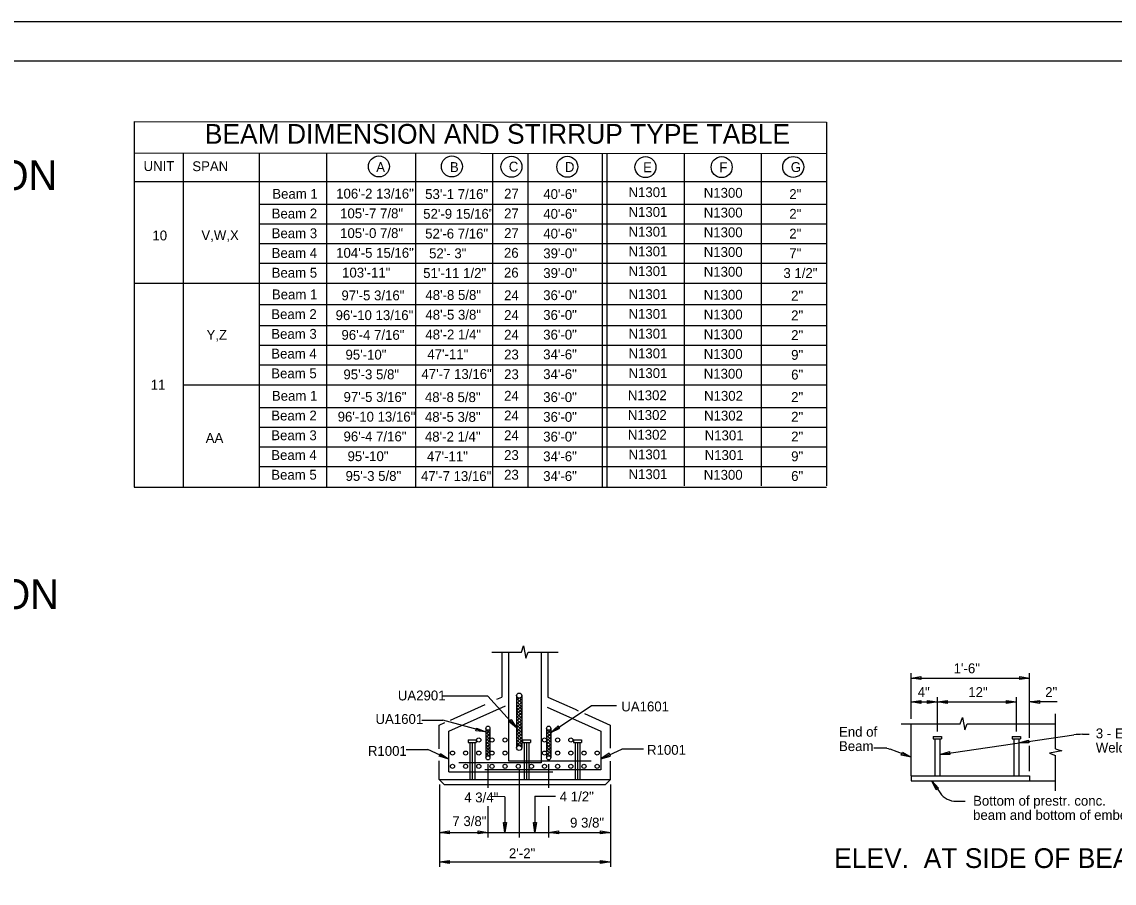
# Model space of a CAD drawing. Extents: x -50.5 to -14.4, y 42.4 to 64.4.
# Drawn here: x -37.02 to -23.18, y 53.54 to 64.45 of the extents above; entities that cross this region are included whole.
import ezdxf

# ---------------------------------------------------------------- set-up
doc = ezdxf.new("R2010")
doc.units = 0
for name, color, linetype in [('BR_AUTO DIMENSION', 7, 'Continuous'), ('BR_BORDER LINES', 7, 'Continuous'), ('BR_CENTER LINES', 7, 'Continuous'), ('BR_PRESTRESSED BEAM', 7, 'Continuous'), ('BR_REBAR', 7, 'Continuous'), ('BR_STRUCTURAL STEEL', 7, 'Continuous'), ('BR_TABLE LINES', 7, 'Continuous'), ('BR_TEXT', 7, 'Continuous'), ('Level 31', 7, 'Continuous')]:
    doc.layers.add(name, color=color, linetype=linetype)

msp = doc.modelspace()

# ---------------------------------------------------------------- linework, layer by layer
at = {"layer": 'BR_AUTO DIMENSION'}
for p, q in [((-31.065, 56.469), (-30.69, 56.469)), ((-30.603, 56.469), (-30.223, 56.469)), ((-25.754, 55.623), (-25.754, 56.2)), ((-24.254, 55.384), (-24.254, 56.2)), ((-25.754, 56.138), (-24.254, 56.138)), ((-31.115, 55.908), (-31.686, 55.908)), ((-31.115, 55.908), (-30.75, 55.509)), ((-25.754, 55.623), (-25.754, 55.899)), ((-25.421, 55.461), (-25.421, 55.899)), ((-24.421, 55.461), (-24.421, 55.899)), ((-30.318, 55.451), (-29.807, 55.789)), ((-29.486, 55.788), (-29.807, 55.789)), ((-25.754, 55.836), (-25.421, 55.836)), ((-25.421, 55.836), (-24.421, 55.836)), ((-23.904, 55.836), (-24.254, 55.836)), ((-23.924, 55.245), (-23.924, 55.686)), ((-31.95, 55.606), (-31.686, 55.607)), ((-31.139, 55.46), (-31.686, 55.607)), ((-25.879, 55.561), (-25.131, 55.561)), ((-25.044, 55.561), (-23.924, 55.561)), ((-25.39, 55.172), (-23.692, 55.42)), ((-23.584, 55.427), (-23.5, 55.427)), ((-32.147, 55.233), (-31.873, 55.233)), ((-31.608, 55.113), (-31.873, 55.233)), ((-29.682, 55.117), (-29.417, 55.237)), ((-29.143, 55.237), (-29.417, 55.237)), ((-26.061, 55.252), (-26.228, 55.252)), ((-25.754, 55.138), (-26.018, 55.237)), ((-24.254, 54.961), (-24.254, 55.281)), ((-23.924, 54.711), (-23.924, 55.158)), ((-31.113, 55.047), (-31.113, 54.751)), ((-30.717, 54.982), (-30.717, 54.122)), ((-30.344, 55.047), (-30.344, 54.751)), ((-31.728, 54.793), (-31.728, 53.748)), ((-29.561, 54.793), (-29.561, 54.286)), ((-25.493, 54.836), (-25.387, 54.686)), ((-30.517, 54.644), (-30.258, 54.645)), ((-30.517, 54.644), (-30.517, 54.184)), ((-31.113, 54.519), (-31.113, 54.122)), ((-30.898, 54.637), (-31.079, 54.638)), ((-30.898, 54.637), (-30.898, 54.184)), ((-30.344, 54.519), (-30.344, 54.122)), ((-25.182, 54.579), (-25.071, 54.579)), ((-29.561, 54.445), (-29.561, 54.122)), ((-31.728, 54.184), (-31.009, 54.184)), ((-31.009, 54.184), (-30.342, 54.184)), ((-30.342, 54.184), (-29.561, 54.184)), ((-29.561, 54.122), (-29.561, 53.748)), ((-31.728, 53.811), (-29.561, 53.811))]:
    msp.add_line(p, q, dxfattribs=at)
for points in [[(-30.69, 56.469), (-30.661, 56.547), (-30.632, 56.392), (-30.603, 56.469)], [(-25.131, 55.561), (-25.102, 55.638), (-25.073, 55.484), (-25.044, 55.561)], [(-23.924, 55.245), (-23.847, 55.216), (-24.001, 55.187), (-23.924, 55.158)]]:
    msp.add_lwpolyline(points, dxfattribs=at)
for points in [[(-25.629, 56.119), (-25.754, 56.138), (-25.629, 56.157)], [(-24.379, 56.157), (-24.254, 56.138), (-24.379, 56.119)], [(-25.629, 55.817), (-25.754, 55.836), (-25.629, 55.855)], [(-25.546, 55.855), (-25.421, 55.836), (-25.546, 55.817)], [(-25.296, 55.817), (-25.421, 55.836), (-25.296, 55.855)], [(-24.546, 55.855), (-24.421, 55.836), (-24.546, 55.817)], [(-24.129, 55.817), (-24.254, 55.836), (-24.129, 55.855)], [(-30.82, 55.614), (-30.75, 55.509), (-30.848, 55.588)], [(-31.257, 55.506), (-31.139, 55.46), (-31.265, 55.469)], [(-30.224, 55.535), (-30.318, 55.451), (-30.204, 55.504)], [(-24.263, 55.317), (-24.39, 55.318), (-24.269, 55.354)], [(-25.865, 55.199), (-25.754, 55.138), (-25.878, 55.164)], [(-25.263, 55.171), (-25.39, 55.172), (-25.269, 55.208)], [(-31.714, 55.182), (-31.608, 55.113), (-31.73, 55.148)], [(-29.576, 55.186), (-29.682, 55.117), (-29.56, 55.152)], [(-25.436, 54.723), (-25.493, 54.836), (-25.406, 54.745)], [(-30.88, 54.309), (-30.898, 54.184), (-30.917, 54.309)], [(-30.499, 54.309), (-30.517, 54.184), (-30.536, 54.309)], [(-31.603, 54.165), (-31.728, 54.184), (-31.603, 54.203)], [(-31.238, 54.203), (-31.113, 54.184), (-31.238, 54.165)], [(-30.219, 54.165), (-30.344, 54.184), (-30.219, 54.203)], [(-29.686, 54.203), (-29.561, 54.184), (-29.686, 54.165)], [(-31.603, 53.792), (-31.728, 53.811), (-31.603, 53.83)], [(-29.686, 53.83), (-29.561, 53.811), (-29.686, 53.792)]]:
    msp.add_lwpolyline(points, close=True, dxfattribs=at)
for centre in [(-32.494, 62.617), (-31.57, 62.617), (-30.815, 62.613), (-30.108, 62.613), (-29.118, 62.609), (-28.153, 62.609), (-27.247, 62.611)]:
    msp.add_circle(centre, 0.133, dxfattribs=at)
for centre, radius, start, end in [((-23.584, 54.677), 0.75, 90, 98.305), ((-26.106, 55.002), 0.25, 69.5828, 90), ((-25.182, 54.829), 0.25, 215.0738, 270)]:
    msp.add_arc(centre, radius, start, end, dxfattribs=at)
at = {"layer": 'BR_BORDER LINES'}
for p, q in [((-15.019, 63.949), (-48.685, 63.949)), ((-35.595, 63.186), (-35.595, 58.558)), ((-35.594, 63.186), (-26.824, 63.179)), ((-26.824, 63.18), (-26.824, 58.572)), ((-35.595, 62.788), (-26.824, 62.78)), ((-29.665, 62.783), (-29.665, 58.558)), ((-29.606, 62.783), (-29.606, 58.558)), ((-35.595, 58.558), (-26.824, 58.558))]:
    msp.add_line(p, q, dxfattribs=at)
at = {"layer": 'BR_CENTER LINES'}
for p, q in [((-31.312, 55.324), (-31.312, 54.855)), ((-30.625, 55.324), (-30.625, 54.855)), ((-29.979, 55.324), (-29.979, 54.855))]:
    msp.add_line(p, q, dxfattribs=at)
at = {"layer": 'BR_PRESTRESSED BEAM'}
for p, q in [((-30.938, 56.469), (-30.938, 55.899)), ((-30.354, 56.469), (-30.354, 55.899)), ((-31.002, 55.87), (-30.938, 55.898)), ((-30.354, 55.898), (-30.01, 55.744)), ((-31.586, 55.607), (-31.146, 55.805)), ((-30.01, 55.744), (-29.971, 55.726)), ((-29.891, 55.69), (-29.563, 55.543)), ((-31.729, 55.543), (-31.657, 55.575)), ((-31.729, 55.242), (-31.729, 55.543)), ((-29.563, 55.543), (-29.563, 55.252)), ((-25.754, 54.899), (-25.754, 55.561)), ((-31.729, 54.855), (-31.729, 55.09)), ((-29.563, 55.085), (-29.563, 54.855)), ((-31.729, 54.855), (-29.563, 54.855)), ((-24.254, 54.836), (-23.924, 54.836))]:
    msp.add_line(p, q, dxfattribs=at)
at = {"layer": 'BR_REBAR'}
for p, q in [((-30.854, 56.469), (-30.854, 55.091)), ((-30.438, 56.469), (-30.438, 55.066)), ((-30.75, 55.917), (-30.75, 55.254)), ((-30.75, 55.901), (-30.747, 55.904)), ((-30.75, 55.885), (-30.685, 55.82)), ((-30.707, 55.886), (-30.685, 55.864)), ((-30.685, 55.917), (-30.685, 55.254)), ((-31.608, 55.466), (-30.889, 55.789)), ((-30.75, 55.857), (-30.722, 55.885)), ((-30.75, 55.813), (-30.685, 55.878)), ((-30.75, 55.841), (-30.685, 55.776)), ((-30.75, 55.768), (-30.685, 55.833)), ((-30.75, 55.804), (-30.685, 55.739)), ((-30.75, 55.724), (-30.685, 55.789)), ((-30.75, 55.768), (-30.685, 55.702)), ((-30.362, 55.771), (-29.682, 55.465)), ((-30.75, 55.68), (-30.685, 55.745)), ((-30.75, 55.731), (-30.685, 55.666)), ((-30.75, 55.636), (-30.685, 55.701)), ((-30.75, 55.694), (-30.685, 55.629)), ((-30.75, 55.592), (-30.685, 55.657)), ((-30.75, 55.657), (-30.685, 55.592)), ((-30.75, 55.62), (-30.685, 55.555)), ((-30.75, 55.547), (-30.685, 55.612)), ((-31.139, 55.504), (-31.139, 55.129)), ((-31.139, 55.488), (-31.087, 55.436)), ((-31.139, 55.473), (-31.129, 55.483)), ((-31.139, 55.429), (-31.087, 55.481)), ((-31.097, 55.483), (-31.087, 55.473)), ((-31.087, 55.504), (-31.087, 55.129)), ((-30.75, 55.583), (-30.685, 55.518)), ((-30.75, 55.503), (-30.685, 55.568)), ((-30.75, 55.547), (-30.685, 55.482)), ((-30.75, 55.459), (-30.685, 55.524)), ((-30.75, 55.51), (-30.685, 55.445)), ((-30.75, 55.415), (-30.685, 55.48)), ((-30.75, 55.473), (-30.685, 55.408)), ((-30.37, 55.504), (-30.37, 55.129)), ((-30.37, 55.488), (-30.318, 55.436)), ((-30.37, 55.473), (-30.36, 55.483)), ((-30.37, 55.429), (-30.318, 55.481)), ((-30.329, 55.483), (-30.318, 55.473)), ((-30.318, 55.504), (-30.318, 55.129)), ((-31.608, 54.952), (-31.608, 55.466)), ((-31.139, 55.452), (-31.087, 55.4)), ((-31.139, 55.384), (-31.087, 55.436)), ((-31.139, 55.415), (-31.087, 55.363)), ((-31.139, 55.34), (-31.087, 55.392)), ((-31.139, 55.378), (-31.087, 55.326)), ((-31.139, 55.296), (-31.087, 55.348)), ((-31.139, 55.341), (-31.087, 55.289)), ((-30.75, 55.371), (-30.685, 55.436)), ((-30.75, 55.436), (-30.685, 55.371)), ((-30.75, 55.399), (-30.685, 55.334)), ((-30.75, 55.326), (-30.685, 55.392)), ((-30.75, 55.362), (-30.685, 55.297)), ((-30.75, 55.282), (-30.685, 55.347)), ((-30.37, 55.452), (-30.318, 55.4)), ((-30.37, 55.384), (-30.318, 55.436)), ((-30.37, 55.415), (-30.318, 55.363)), ((-30.37, 55.34), (-30.318, 55.392)), ((-30.37, 55.378), (-30.318, 55.326)), ((-30.37, 55.296), (-30.318, 55.348)), ((-30.37, 55.341), (-30.318, 55.289)), ((-29.682, 55.465), (-29.682, 54.975)), ((-31.139, 55.252), (-31.087, 55.304)), ((-31.139, 55.304), (-31.087, 55.252)), ((-31.139, 55.267), (-31.087, 55.215)), ((-31.139, 55.208), (-31.087, 55.26)), ((-31.139, 55.231), (-31.087, 55.179)), ((-31.139, 55.163), (-31.087, 55.216)), ((-31.139, 55.194), (-31.087, 55.142)), ((-30.75, 55.326), (-30.691, 55.267)), ((-30.75, 55.289), (-30.735, 55.274)), ((-30.709, 55.279), (-30.685, 55.303)), ((-30.37, 55.252), (-30.318, 55.304)), ((-30.37, 55.304), (-30.318, 55.252)), ((-30.37, 55.267), (-30.318, 55.215)), ((-30.37, 55.208), (-30.318, 55.26)), ((-30.37, 55.231), (-30.318, 55.179)), ((-30.37, 55.163), (-30.318, 55.216)), ((-30.37, 55.194), (-30.318, 55.142)), ((-30.438, 55.066), (-31.483, 55.066)), ((-31.139, 55.157), (-31.131, 55.148)), ((-31.105, 55.154), (-31.087, 55.171)), ((-30.854, 55.091), (-29.807, 55.091)), ((-30.37, 55.157), (-30.362, 55.148)), ((-30.336, 55.154), (-30.318, 55.171)), ((-31.608, 54.952), (-30.29, 54.952)), ((-29.682, 54.975), (-31.153, 54.975))]:
    msp.add_line(p, q, dxfattribs=at)
for centre, radius in [((-30.717, 55.917), 0.0326), ((-31.113, 55.504), 0.026), ((-30.344, 55.504), 0.026), ((-31.229, 55.355), 0.026), ((-31.062, 55.355), 0.026), ((-30.896, 55.355), 0.026), ((-30.397, 55.355), 0.026), ((-30.23, 55.355), 0.026), ((-30.063, 55.355), 0.026), ((-31.562, 55.189), 0.026), ((-31.396, 55.189), 0.026), ((-31.229, 55.189), 0.026), ((-31.062, 55.189), 0.026), ((-30.896, 55.189), 0.026), ((-30.717, 55.254), 0.0326), ((-30.397, 55.189), 0.026), ((-30.23, 55.189), 0.026), ((-30.063, 55.189), 0.026), ((-29.897, 55.189), 0.026), ((-29.73, 55.189), 0.026), ((-31.113, 55.129), 0.026), ((-30.344, 55.129), 0.026), ((-31.562, 55.022), 0.026), ((-31.396, 55.022), 0.026), ((-31.229, 55.022), 0.026), ((-31.062, 55.022), 0.026), ((-30.896, 55.022), 0.026), ((-30.729, 55.022), 0.026), ((-30.562, 55.022), 0.026), ((-30.397, 55.022), 0.026), ((-30.23, 55.022), 0.026), ((-30.063, 55.022), 0.026), ((-29.897, 55.022), 0.026), ((-29.73, 55.022), 0.026)]:
    msp.add_circle(centre, radius, dxfattribs=at)
at = {"layer": 'BR_STRUCTURAL STEEL'}
for p, q in [((-31.364, 55.355), (-31.364, 55.324)), ((-31.364, 55.355), (-31.26, 55.355)), ((-31.26, 55.355), (-31.26, 55.324)), ((-30.677, 55.355), (-30.573, 55.355)), ((-30.677, 55.355), (-30.677, 55.324)), ((-30.573, 55.355), (-30.573, 55.324)), ((-30.031, 55.355), (-29.927, 55.355)), ((-30.031, 55.355), (-30.031, 55.324)), ((-29.927, 55.355), (-29.927, 55.324)), ((-25.473, 55.399), (-25.369, 55.399)), ((-25.473, 55.399), (-25.473, 55.368)), ((-25.473, 55.368), (-25.369, 55.368)), ((-25.452, 55.368), (-25.452, 54.899)), ((-25.39, 55.368), (-25.39, 54.899)), ((-25.369, 55.399), (-25.369, 55.368)), ((-24.473, 55.399), (-24.369, 55.399)), ((-24.473, 55.399), (-24.473, 55.368)), ((-24.473, 55.368), (-24.369, 55.368)), ((-24.452, 55.368), (-24.452, 54.899)), ((-24.452, 55.368), (-24.452, 54.899)), ((-24.39, 55.368), (-24.39, 54.899)), ((-24.369, 55.399), (-24.369, 55.368)), ((-31.364, 55.324), (-31.26, 55.324)), ((-31.343, 55.324), (-31.343, 54.855)), ((-31.281, 55.324), (-31.281, 54.855)), ((-30.677, 55.324), (-30.573, 55.324)), ((-30.656, 55.324), (-30.656, 54.855)), ((-30.593, 55.324), (-30.593, 54.855)), ((-30.031, 55.324), (-29.927, 55.324)), ((-30.01, 55.324), (-30.01, 54.855)), ((-29.948, 55.324), (-29.948, 54.855)), ((-31.666, 54.793), (-31.729, 54.855)), ((-31.666, 54.793), (-29.625, 54.793)), ((-29.625, 54.793), (-29.562, 54.855)), ((-25.754, 54.899), (-24.254, 54.899)), ((-25.754, 54.899), (-25.754, 54.836)), ((-25.754, 54.836), (-24.254, 54.836)), ((-24.254, 54.899), (-24.254, 54.836))]:
    msp.add_line(p, q, dxfattribs=at)
at = {"layer": 'BR_TABLE LINES'}
for p, q in [((-34.974, 62.788), (-34.974, 58.558)), ((-34.01, 62.788), (-34.01, 58.558)), ((-33.158, 62.788), (-33.158, 58.558)), ((-32.031, 62.788), (-32.031, 58.558)), ((-31.054, 62.783), (-31.054, 58.558)), ((-30.606, 62.783), (-30.606, 58.558)), ((-29.606, 62.783), (-29.606, 58.572)), ((-28.63, 62.778), (-28.63, 58.572)), ((-27.653, 62.781), (-27.653, 58.572)), ((-35.595, 62.429), (-26.824, 62.429)), ((-34.01, 62.141), (-26.824, 62.141)), ((-34.01, 61.891), (-26.824, 61.891)), ((-34.01, 61.641), (-26.824, 61.641)), ((-34.01, 61.391), (-26.824, 61.391)), ((-35.595, 61.138), (-26.824, 61.138)), ((-34.01, 60.87), (-26.824, 60.87)), ((-34.01, 60.604), (-26.824, 60.604)), ((-34.01, 60.354), (-26.824, 60.354)), ((-28.63, 60.219), (-28.63, 58.572)), ((-34.01, 60.104), (-26.824, 60.104)), ((-34.974, 59.854), (-26.824, 59.854)), ((-30.583, 59.854), (-26.824, 59.854)), ((-34.01, 59.566), (-26.824, 59.566)), ((-34.01, 59.316), (-26.824, 59.316)), ((-34.01, 59.066), (-26.824, 59.066)), ((-34.01, 58.816), (-26.824, 58.816))]:
    msp.add_line(p, q, dxfattribs=at)
at = {"layer": 'Level 31'}
msp.add_lwpolyline([(-50.519, 42.449), (-14.519, 42.449), (-14.519, 64.449), (-50.519, 64.449)], close=True, dxfattribs=at)

# ---------------------------------------------------------------- texts
at = {"layer": 'BR_AUTO DIMENSION'}
for s, p in [('1\'-6"', (-25.215, 56.2)), ('4"', (-25.67, 55.899)), ('12"', (-25.03, 55.899)), ('2"', (-24.056, 55.899)), ('4 3/4"', (-31.413, 54.565)), ('4 1/2"', (-30.203, 54.577)), ('7 3/8"', (-31.563, 54.265)), ('9 3/8"', (-30.073, 54.246)), ('2\'-2"', (-30.847, 53.858))]:
    msp.add_text(s, height=0.125, dxfattribs=at).set_placement(p)
at = {"layer": 'BR_TEXT'}
for s, height, p in [('BEAM DIMENSION AND STIRRUP TYPE TABLE', 0.25, (-34.698, 62.905)), ('UNIT 10 BEAM CAMBER AND DEFLECTION', 0.375, (-46.794, 62.318)), ('C', 0.125, (-30.849, 62.553)), ('D', 0.125, (-30.138, 62.548)), ('E', 0.125, (-29.148, 62.544)), ('F', 0.125, (-28.183, 62.544)), ('G', 0.125, (-27.278, 62.547)), ('Beam 1', 0.125, (-33.844, 62.209)), ('106\'-2 13/16"', 0.125, (-33.035, 62.211)), ('53\'-1 7/16"', 0.125, (-31.908, 62.205)), ('27', 0.125, (-30.908, 62.211)), ('40\'-6"', 0.125, (-30.412, 62.205)), ('N1301', 0.125, (-29.333, 62.229)), ('N1300', 0.125, (-28.38, 62.221)), ('2"', 0.125, (-27.297, 62.205)), ('Beam 2', 0.125, (-33.852, 61.959)), ('105\'-7 7/8"', 0.125, (-32.985, 61.961)), ('52\'-9 15/16"', 0.125, (-31.933, 61.955)), ('27', 0.125, (-30.908, 61.961)), ('40\'-6"', 0.125, (-30.412, 61.955)), ('N1301', 0.125, (-29.333, 61.979)), ('N1300', 0.125, (-28.38, 61.971)), ('2"', 0.125, (-27.297, 61.955)), ('Beam 3', 0.125, (-33.852, 61.709)), ('105\'-0 7/8"', 0.125, (-32.985, 61.711)), ('52\'-6 7/16"', 0.125, (-31.908, 61.705)), ('27', 0.125, (-30.908, 61.711)), ('N1301', 0.125, (-29.333, 61.729)), ('N1300', 0.125, (-28.38, 61.721)), ('40\'-6"', 0.125, (-30.412, 61.705)), ('2"', 0.125, (-27.297, 61.705)), ('Beam 4', 0.125, (-33.852, 61.459)), ('104\'-5 15/16"', 0.125, (-33.035, 61.461)), ('52\'- 3"', 0.125, (-31.858, 61.455)), ('26', 0.125, (-30.91, 61.461)), ('39\'-0"', 0.125, (-30.412, 61.455)), ('N1301', 0.125, (-29.333, 61.479)), ('N1300', 0.125, (-28.38, 61.471)), ('7"', 0.125, (-27.297, 61.455)), ('Beam 5', 0.125, (-33.852, 61.209)), ('103\'-11"', 0.125, (-32.96, 61.211)), ('51\'-11 1/2"', 0.125, (-31.933, 61.205)), ('26', 0.125, (-30.91, 61.211)), ('39\'-0"', 0.125, (-30.412, 61.205)), ('N1301', 0.125, (-29.333, 61.229)), ('N1300', 0.125, (-28.38, 61.221)), ('3 1/2"', 0.125, (-27.371, 61.205)), ('Beam 1', 0.125, (-33.849, 60.935)), ('97\'-5 3/16"', 0.125, (-32.968, 60.922)), ('48\'-8 5/8"', 0.125, (-31.905, 60.927)), ('24', 0.125, (-30.908, 60.924)), ('36\'-0"', 0.125, (-30.413, 60.925)), ('N1301', 0.125, (-29.333, 60.938)), ('N1300', 0.125, (-28.38, 60.93)), ('2"', 0.125, (-27.273, 60.919)), ('Beam 2', 0.125, (-33.857, 60.685)), ('96\'-10 13/16"', 0.125, (-33.042, 60.672)), ('48\'-5 3/8"', 0.125, (-31.905, 60.677)), ('24', 0.125, (-30.908, 60.674)), ('36\'-0"', 0.125, (-30.413, 60.675)), ('N1301', 0.125, (-29.333, 60.688)), ('N1300', 0.125, (-28.38, 60.68)), ('2"', 0.125, (-27.273, 60.669)), ('Beam 3', 0.125, (-33.857, 60.435)), ('96\'-4 7/16"', 0.125, (-32.968, 60.422)), ('48\'-2 1/4"', 0.125, (-31.905, 60.427)), ('24', 0.125, (-30.908, 60.424)), ('36\'-0"', 0.125, (-30.413, 60.425)), ('N1301', 0.125, (-29.333, 60.438)), ('N1300', 0.125, (-28.38, 60.43)), ('2"', 0.125, (-27.273, 60.419)), ('N1301', 0.125, (-29.333, 60.188)), ('Beam 4', 0.125, (-33.857, 60.185)), ('95\'-10"', 0.125, (-32.917, 60.172)), ('47\'-11"', 0.125, (-31.88, 60.177)), ('23', 0.125, (-30.908, 60.174)), ('34\'-6"', 0.125, (-30.413, 60.175)), ('N1300', 0.125, (-28.38, 60.18)), ('9"', 0.125, (-27.273, 60.169)), ('Beam 5', 0.125, (-33.857, 59.935)), ('95\'-3 5/8"', 0.125, (-32.943, 59.922)), ('47\'-7 13/16"', 0.125, (-31.955, 59.927)), ('23', 0.125, (-30.908, 59.924)), ('34\'-6"', 0.125, (-30.413, 59.925)), ('N1301', 0.125, (-29.333, 59.938)), ('N1300', 0.125, (-28.38, 59.93)), ('6"', 0.125, (-27.273, 59.919)), ('Beam 1', 0.125, (-33.849, 59.651)), ('97\'-5 3/16"', 0.125, (-32.942, 59.636)), ('48\'-8 5/8"', 0.125, (-31.911, 59.634)), ('24', 0.125, (-30.908, 59.651)), ('36\'-0"', 0.125, (-30.413, 59.634)), ('N1302', 0.125, (-29.341, 59.658)), ('N1302', 0.125, (-28.376, 59.65)), ('2"', 0.125, (-27.273, 59.635)), ('Beam 2', 0.125, (-33.857, 59.401)), ('96\'-10 13/16"', 0.125, (-33.016, 59.386)), ('48\'-5 3/8"', 0.125, (-31.911, 59.384)), ('24', 0.125, (-30.908, 59.401)), ('36\'-0"', 0.125, (-30.413, 59.384)), ('N1302', 0.125, (-29.341, 59.408)), ('N1302', 0.125, (-28.376, 59.4)), ('2"', 0.125, (-27.273, 59.385)), ('Beam 3', 0.125, (-33.857, 59.151)), ('96\'-4 7/16"', 0.125, (-32.942, 59.136)), ('48\'-2 1/4"', 0.125, (-31.911, 59.134)), ('24', 0.125, (-30.908, 59.151)), ('36\'-0"', 0.125, (-30.413, 59.134)), ('N1302', 0.125, (-29.341, 59.158)), ('N1301', 0.125, (-28.368, 59.15)), ('2"', 0.125, (-27.273, 59.135)), ('Beam 4', 0.125, (-33.857, 58.901)), ('95\'-10"', 0.125, (-32.891, 58.886)), ('47\'-11"', 0.125, (-31.886, 58.884)), ('23', 0.125, (-30.908, 58.901)), ('34\'-6"', 0.125, (-30.413, 58.884)), ('N1301', 0.125, (-29.333, 58.908)), ('N1301', 0.125, (-28.368, 58.9)), ('9"', 0.125, (-27.273, 58.885)), ('Beam 5', 0.125, (-33.857, 58.651)), ('95\'-3 5/8"', 0.125, (-32.916, 58.636)), ('47\'-7 13/16"', 0.125, (-31.961, 58.634)), ('23', 0.125, (-30.908, 58.651)), ('34\'-6"', 0.125, (-30.413, 58.634)), ('N1301', 0.125, (-29.333, 58.658)), ('N1300', 0.125, (-28.38, 58.65)), ('6"', 0.125, (-27.273, 58.635)), ('UNIT 11 BEAM CAMBER AND DEFLECTION', 0.375, (-46.773, 57.013)), ('UA2901', 0.125, (-32.254, 55.856)), ('UA1601', 0.125, (-29.424, 55.717)), ('UA1601', 0.125, (-32.537, 55.558)), ('End of', 0.125, (-26.667, 55.396)), ('3 - Electrically', 0.125, (-23.415, 55.376)), ('Beam', 0.125, (-26.667, 55.215)), ('R1001', 0.125, (-32.633, 55.154)), ('R1001', 0.125, (-29.098, 55.167)), ('Welded Studs', 0.125, (-23.415, 55.196)), ('Bottom of prestr. conc.', 0.125, (-24.969, 54.523)), ('beam and bottom of embedded P', 0.125, (-24.969, 54.343)), ('ELEV.  AT SIDE OF BEAM', 0.25, (-26.728, 53.734))]:
    msp.add_text(s, height=height, dxfattribs=at).set_placement(p)
for s, p in [('UNIT', (-35.474, 62.56)), ('SPAN', (-34.857, 62.558)), ('A', (-32.528, 62.547)), ('B', (-31.595, 62.547)), ('10', (-35.362, 61.681)), ('V,W,X', (-34.742, 61.685)), ('Y,Z', (-34.677, 60.423)), ('11', (-35.383, 59.791)), ('AA', (-34.687, 59.117))]:
    msp.add_text(s, height=0.125, rotation=360, dxfattribs=at).set_placement(p)

doc.saveas('drawing.dxf')
